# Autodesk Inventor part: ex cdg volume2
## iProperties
Created: 2002-05
Part Number: ex cdg volume2
Material: Delrin - Noir
Document SubType Name: Modélisation
Designer: Administrateur
Control State: 0
Master: False
Checked Out: False
Shininess: 20.0
Angle Display Precision: 2
Document Length Units: 11269
Document Angle Units: 11279
Document Time Units: 11290
Document Mass Units: 11283
Document Length Units Precision: 3
Document Angle Units Precision: 2
Density: 7.839999999999999
Volumn: 82.46127878423158
Area: 138.67255756846316
PropertySet Name: Model Information
Author: Administrateur
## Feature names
1. Extrusion1
2. Extrusion2
3. Extrusion3
